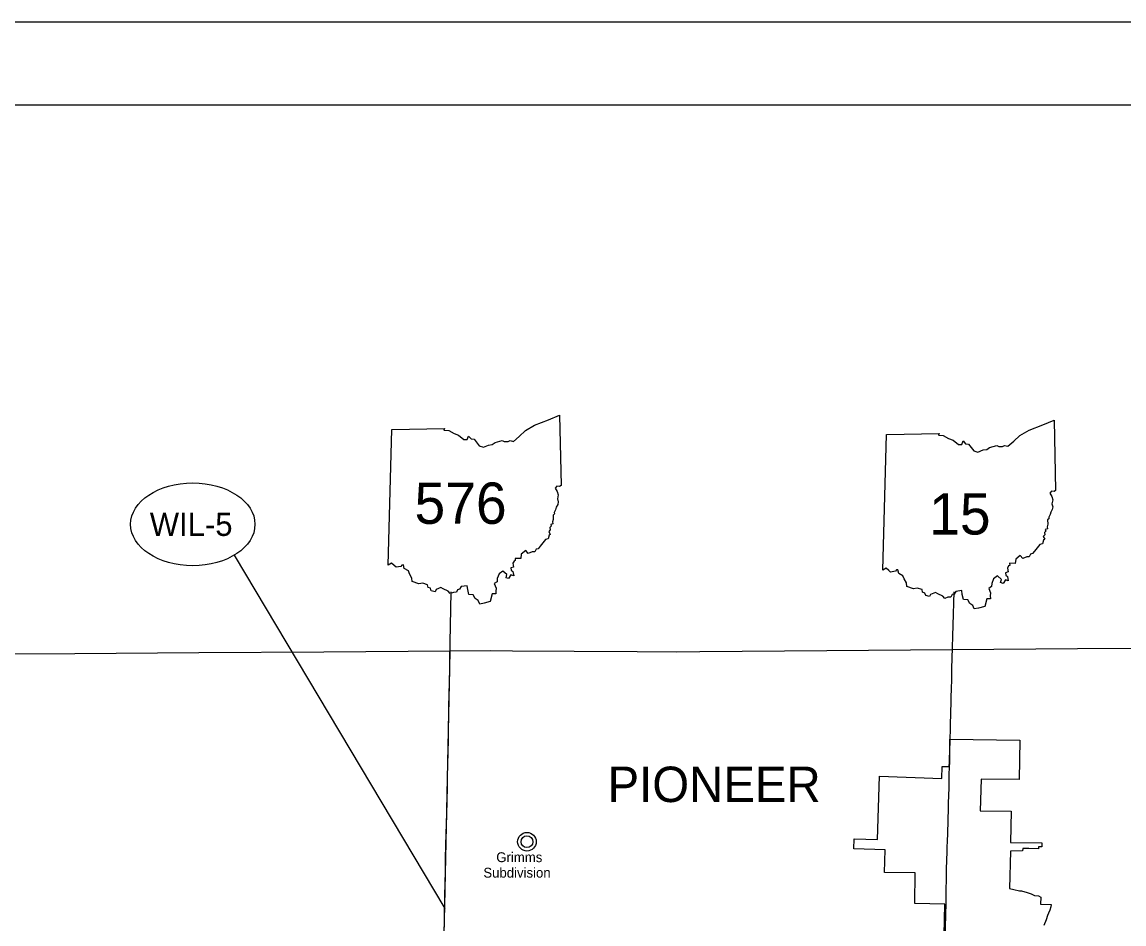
# Model space of a CAD drawing. Extents: x -66 to 795, y 0 to 440.
# Drawn here: x 250.6 to 383.6, y 331.1 to 440 of the extents above; entities that cross this region are included whole.
import ezdxf

# ---------------------------------------------------------------- set-up
doc = ezdxf.new("R2010")
doc.units = 0
for name, color, linetype in [('DV_X_Corp_Line', 7, 'Continuous'), ('GM_X_Corporation_Text', 7, 'Continuous'), ('GM_X_County', 7, 'Continuous'), ('GM_X_State_Route', 7, 'Continuous'), ('PV_P_Text', 7, 'Continuous'), ('RD_P_Fence', 7, 'Continuous'), ('SH_Border', 7, 'Continuous'), ('SH_Cut_Line', 7, 'Continuous'), ('SH_Data', 7, 'Continuous')]:
    doc.layers.add(name, color=color, linetype=linetype)

msp = doc.modelspace()

# ---------------------------------------------------------------- linework, layer by layer
at = {"layer": 'DV_X_Corp_Line'}
msp.add_lwpolyline([(361.89, 329.79), (361.97, 333.52), (358.38, 333.61), (358.4, 337.3), (354.68, 337.37), (354.78, 340.11), (350.99, 340.21), (351.03, 341.43), (353.86, 341.36), (354.1, 348.97), (361.61, 348.72), (361.67, 350.17), (362.52, 350.14), (362.54, 350.7), (362.58, 352.4), (362.6, 353.33), (362.6, 353.44), (371.04, 353.34), (370.94, 348.6), (366.36, 348.63), (366.23, 344.82), (369.99, 344.75), (369.92, 340.99), (373.71, 340.95), (373.7, 340.45), (373.29, 340.45), (373.29, 340.23), (372.12, 340.25), (371.38, 340.24), (371.37, 339.96), (369.89, 339.95), (369.8, 335.43), (370.33, 335.29), (370.98, 335.13), (371.25, 335.16), (371.92, 334.93), (372.39, 334.79), (372.82, 334.58), (373.27, 334.54), (373.57, 334.39), (373.54, 333.52), (374.83, 333.48), (374.79, 333.23), (374.65, 332.81), (374.5, 332.47), (374.38, 332.15), (374.21, 331.65), (373.95, 330.96)], dxfattribs=at)
for radius in [1.12, 0.71]:
    msp.add_circle((311.54, 341.07), radius, dxfattribs=at)
at = {"layer": 'GM_X_County'}
msp.add_lwpolyline([(392.99, 364.44), (377.99, 364.37), (362.85, 364.23), (347.73, 364.11), (332.43, 363.99), (329.61, 363.97), (324.86, 364), (317.26, 364.04), (309.78, 364.09), (307.12, 364.11), (302.27, 364.07), (287.03, 363.97), (271.95, 363.87), (256.96, 363.76), (241.88, 363.65)], dxfattribs=at)
at = {"layer": 'GM_X_State_Route'}
for points in [[(301.56, 330), (301.58, 331.46), (301.61, 332.8), (301.63, 333.98), (301.64, 334.67), (301.67, 335.96), (301.71, 337.63), (301.73, 339.06), (301.76, 340.64), (301.8, 341.98), (301.81, 342.23), (301.83, 343.01), (301.87, 344.34), (301.9, 346.01), (301.94, 347.64), (301.96, 348.97), (301.99, 350.36), (302.02, 351.88), (302.06, 353.36), (302.09, 354.92), (302.12, 356.38), (302.12, 357.14), (302.13, 357.29), (302.13, 357.38), (302.15, 358.84), (302.19, 360.32), (302.22, 361.65), (302.25, 363.05), (302.41, 371.25)], [(363.05, 371.22), (362.82, 363.2), (362.79, 362.03), (362.77, 360.75), (362.73, 359.44), (362.71, 358.58)], [(362.71, 358.58), (362.71, 358.57), (362.69, 357.98), (362.66, 356.58), (362.65, 356.2), (362.64, 355.59), (362.62, 354.51), (362.6, 353.63), (362.6, 353.63)], [(362.59, 353.48), (362.59, 353.35), (362.56, 351.96), (362.53, 350.55), (362.51, 350.15)], [(362.6, 353.63), (362.59, 353.48), (362.59, 353.48)], [(362.51, 350.15), (362.51, 350.15), (362.48, 349.09), (362.48, 348.79), (362.48, 348.79)], [(362.48, 348.79), (362.45, 347.74), (362.45, 347.73)], [(362.45, 347.73), (362.45, 347.71), (362.41, 346.54), (362.4, 345.83), (362.4, 345.78), (362.38, 344.95), (362.37, 344.84), (362.35, 343.92), (362.34, 343.34), (362.3, 342.34), (362.29, 342.11), (362.29, 342.09)], [(362.29, 342.09), (362.29, 342.06), (362.26, 341.16), (362.25, 340.88), (362.24, 340.67), (362.23, 339.99), (362.23, 339.98)], [(362.23, 339.98), (362.22, 339.92), (362.22, 339.77), (362.19, 338.93), (362.18, 338.69), (362.17, 338.48)], [(362.17, 338.48), (362.16, 338.12), (362.15, 337.31), (362.15, 337.21), (362.14, 336.39), (362.12, 335.42), (362.11, 334.35), (362.09, 333.53)], [(362.09, 333.53), (362.09, 333.53), (362.09, 333.38), (362.07, 332.48)], [(362.07, 332.48), (362.06, 332.18), (362.03, 330.83), (362.01, 329.88), (361.99, 328.75), (361.99, 327.1), (361.97, 326.03)]]:
    msp.add_lwpolyline(points, dxfattribs=at)
at = {"layer": 'PV_P_Text'}
for p, q in [((294.8, 374.45), (295.25, 390.82)), ((354.49, 373.85), (354.94, 390.23))]:
    msp.add_line(p, q, dxfattribs=at)
for points in [[(295.25, 390.82), (301.61, 390.93), (301.51, 390.73), (302.11, 390.69), (302.74, 390.34), (303.28, 390.12), (303.94, 389.6), (304.34, 389.6), (304.5, 390.03), (304.8, 389.7), (305.16, 389.64), (305.78, 388.86), (306.29, 388.69), (306.91, 388.95), (307.36, 389), (307.7, 389.26), (308.57, 389.49), (308.81, 389.36), (309.27, 389.38), (309.51, 389.48), (309.91, 389.39), (310.62, 389.99), (311.35, 390.69), (312.47, 391.35), (314.14, 391.98), (315.47, 392.54), (315.66, 384.05)], [(354.94, 390.23), (361.3, 390.33), (361.2, 390.14), (361.8, 390.09), (362.43, 389.74), (362.97, 389.52), (363.63, 389), (364.03, 389.01), (364.19, 389.44), (364.49, 389.11), (364.85, 389.05), (365.47, 388.26), (365.98, 388.09), (366.59, 388.36), (367.05, 388.41), (367.39, 388.67), (368.26, 388.9), (368.5, 388.76), (368.96, 388.79), (369.2, 388.89), (369.6, 388.8), (370.31, 389.4), (371.04, 390.1), (372.16, 390.76), (373.83, 391.39), (375.16, 391.95), (375.35, 383.45)], [(315.66, 384.05), (315.47, 383.93), (315.16, 383.98), (314.96, 383.74), (315.21, 383.35), (315.33, 382.93), (315.22, 382.46), (315.33, 382.08), (315.26, 381.76), (315.07, 381.44), (315, 381.14), (314.84, 380.82), (314.85, 380.64), (314.7, 380.5), (314.72, 379.97), (314.64, 379.67), (314.67, 379.42), (314.42, 379.35), (314.48, 379.14), (314.32, 378.98), (314.35, 378.7), (314.17, 378.52), (314.35, 378.17), (314.21, 378.06), (314.09, 377.62), (313.77, 377.53), (313.12, 376.74), (312.89, 376.44), (312.64, 376.37), (312.49, 376.06), (312.18, 376.06), (311.7, 375.84), (311.39, 376.21), (310.85, 375.77), (310.79, 375.26), (310.11, 375.27), (310.13, 375.02), (309.98, 374.94), (309.84, 374.68), (309.92, 374.22), (309.6, 374.11), (309.64, 373.84), (309.85, 373.68), (309.94, 373.17), (309.6, 373.27), (309.32, 372.84), (309.03, 372.94), (309.13, 373.31), (308.64, 373.74), (308.18, 373.39), (307.95, 372.83), (307.94, 372.45), (307.6, 372.23), (307.82, 371.69), (307.78, 371.33), (307.79, 370.98), (307.36, 370.99), (307.1, 370.05)], [(375.35, 383.45), (375.16, 383.33), (374.85, 383.39), (374.65, 383.15), (374.9, 382.75), (375.02, 382.33), (374.91, 381.87), (375.02, 381.49), (374.95, 381.17), (374.76, 380.85), (374.69, 380.55), (374.53, 380.23), (374.54, 380.05), (374.38, 379.91), (374.41, 379.38), (374.33, 379.08), (374.36, 378.83), (374.11, 378.76), (374.17, 378.55), (374.01, 378.39), (374.04, 378.11), (373.86, 377.93), (374.04, 377.58), (373.9, 377.46), (373.78, 377.03), (373.46, 376.94), (372.81, 376.15), (372.58, 375.85), (372.32, 375.77), (372.18, 375.47), (371.87, 375.46), (371.39, 375.25), (371.08, 375.62), (370.54, 375.18), (370.48, 374.67), (369.8, 374.68), (369.82, 374.42), (369.67, 374.35), (369.53, 374.09), (369.61, 373.63), (369.29, 373.51), (369.33, 373.25), (369.54, 373.08), (369.63, 372.57), (369.29, 372.68), (369.01, 372.25), (368.72, 372.35), (368.82, 372.71), (368.33, 373.15), (367.87, 372.8), (367.64, 372.24), (367.63, 371.86), (367.29, 371.63), (367.51, 371.1), (367.47, 370.74), (367.48, 370.39), (367.05, 370.4), (366.79, 369.46)], [(307.1, 370.05), (306.36, 369.87), (305.85, 369.76), (305.66, 370.19), (305.3, 370.42), (305.06, 370.85), (304.53, 370.91), (304.4, 371.5), (304.34, 371.97), (303.62, 371.86), (303.42, 371.56), (303.17, 371.48), (303.02, 371.19), (302.67, 371.17), (302.29, 371.03), (302.05, 371.32), (301.44, 371.61), (301.16, 371.76), (300.58, 371.52), (300.46, 371.25), (300, 371.37), (299.89, 371.68), (299.61, 371.77), (299.55, 372.09), (298.96, 372.27), (298.5, 372.2), (297.7, 372.46), (297.65, 372.89), (297.38, 373.41), (297.24, 373.78), (296.73, 374.05), (296.63, 374.49), (296.46, 374.47), (296.32, 374.3), (295.75, 374.22), (295.53, 374.39), (295.21, 374.69), (294.8, 374.45)], [(366.79, 369.46), (366.05, 369.28), (365.54, 369.17), (365.35, 369.6), (364.99, 369.82), (364.75, 370.25), (364.22, 370.31), (364.09, 370.9), (364.03, 371.38), (363.31, 371.26), (363.11, 370.97), (362.86, 370.89), (362.71, 370.6), (362.36, 370.57), (361.98, 370.43), (361.74, 370.72), (361.12, 371.01), (360.85, 371.16), (360.27, 370.93), (360.15, 370.65), (359.69, 370.78), (359.58, 371.08), (359.3, 371.18), (359.24, 371.5), (358.65, 371.68), (358.19, 371.61), (357.39, 371.87), (357.34, 372.3), (357.07, 372.82), (356.93, 373.18), (356.42, 373.46), (356.32, 373.89), (356.15, 373.88), (356.01, 373.71), (355.44, 373.62), (355.22, 373.8), (354.9, 374.1), (354.49, 373.85)]]:
    msp.add_lwpolyline(points, dxfattribs=at)
at = {"layer": 'RD_P_Fence'}
msp.add_lwpolyline([(300.96, 304.47), (301.62, 333.36), (302.27, 364.02)], dxfattribs=at)
at = {"layer": 'SH_Border'}
msp.add_lwpolyline([(30, 430), (670, 430), (670, 10), (30, 10)], close=True, dxfattribs=at)
at = {"layer": 'SH_Cut_Line'}
msp.add_lwpolyline([(0, 0), (680, 0), (680, 440), (0, 440)], close=True, dxfattribs=at)
at = {"layer": 'SH_Data'}
msp.add_line((276.21, 375.65), (301.62, 333.01), dxfattribs=at)
msp.add_ellipse((271.21, 379.38), major_axis=(7.5, 0), ratio=0.666667, dxfattribs=at)

# ---------------------------------------------------------------- texts
at = {"layer": 'DV_X_Corp_Line'}
for s, height, p in [('Grimms', 1.188, (307.84, 338.61)), ('Subdivision', 1.1875, (306.28, 336.74))]:
    msp.add_text(s, height=height, rotation=0, dxfattribs=at).set_placement(p)
at = {"layer": 'GM_X_Corporation_Text'}
msp.add_text('PIONEER', height=4.275, rotation=0, dxfattribs=at).set_placement((321.27, 345.86))
at = {"layer": 'PV_P_Text'}
for s, p in [('576', (297.97, 379.44)), ('15', (360.09, 378.15))]:
    msp.add_text(s, height=4.987, dxfattribs=at).set_placement(p)
at = {"layer": 'SH_Data'}
msp.add_text('WIL-5', height=2.8, dxfattribs=at).set_placement((266.02, 377.98))

doc.saveas('drawing.dxf')
